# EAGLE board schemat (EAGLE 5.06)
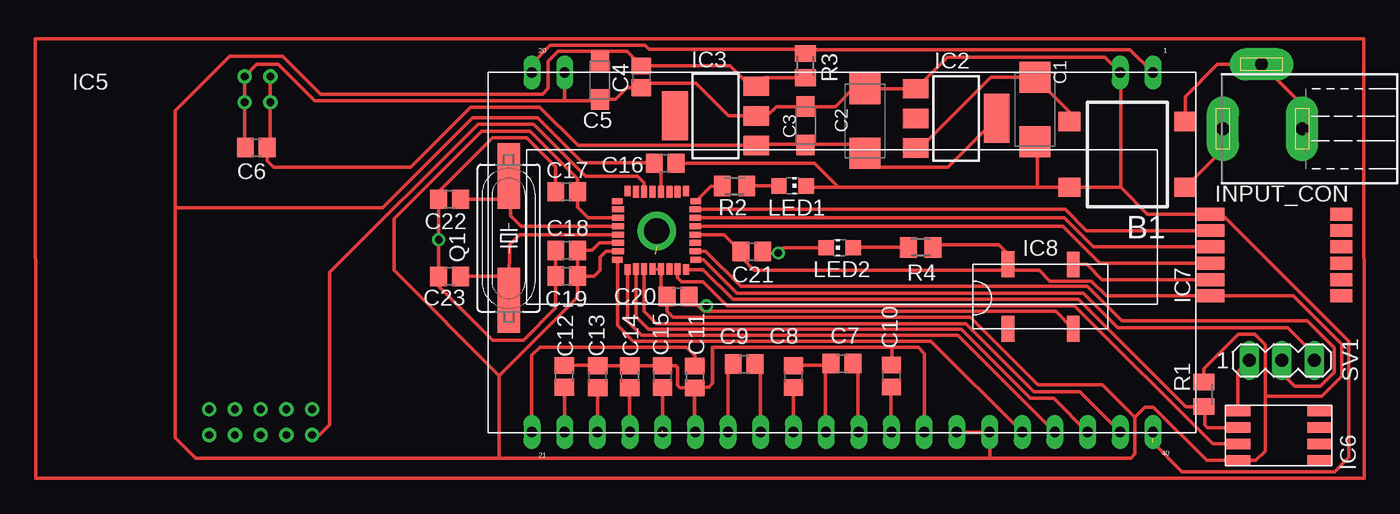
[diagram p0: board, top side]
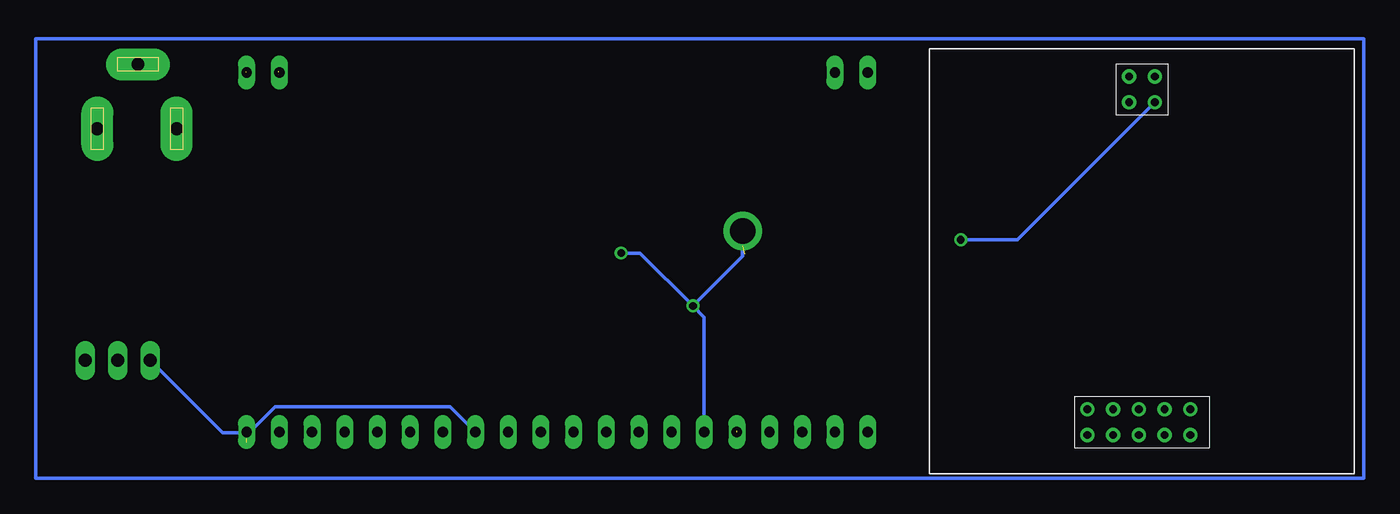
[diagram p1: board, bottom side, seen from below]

No outline drawn. Coordinates in mm, seen from the top.
Copper layers (1*16): Top 0.035mm / dielectric 1.5mm / Bottom 0.035mm
Design rules "default": minimum track width 10mil, minimum drill 24mil, track to track 8mil, track to pad 8mil, pad to pad 8mil, via to via 8mil, smd to smd 8mil, copper to edge 40mil, drill to drill 8mil, minimum pad ring 10mil, minimum via ring 8mil, stop-mask expansion 4mil, vias tented up to drill 0mil, thermal gap 10mil

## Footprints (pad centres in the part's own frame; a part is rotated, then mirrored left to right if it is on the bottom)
B40S = smd 1.5 x 1.7: + -2.55,-4.5; - 2.55,-4.5; AC1 -2.55,4.5; AC2 2.55,4.5
SMC_C = smd 2.4 x 2.4: + -2.5,0; - 2.5,0
SMC_A = smd 1.6 x 1.4: + -1.5,0; - 1.5,0
C0805 = smd 1.3 x 1.5: 1 -0.85,0; 2 0.85,0
SOT223 = smd 1.5 x 2: 1 -2.3,-3.15; 2 0,-3.15; 3 2.3,-3.15 | smd 3.8 x 2: 4 0,3.15
733980-62 = drill 1 pad 2.5 long: 1 0,8.57; 2 0,2.42; 3 5,5.57
CHIP-LED0805 = smd 1.2 x 1.2: A 0,-1.05; C 0,1.05
SM49 = smd 5.08 x 1.778: 1 -4.826,0; 2 4.826,0
M0805 = smd 1.3 x 1.6: 1 -0.95,0; 2 0.95,0
MA03-1 = drill 1.016 long: 1 -2.54,0; 2 0,0; 3 2.54,0
EFM32G210 = smd 0.82 x 0.47: 1 -0.05,0; 8 -0.05,-4.55; 17 6.05,-4.55; 24 6.05,0 | smd 0.92 x 0.47: 2 0,-0.65; 3 0,-1.3; 4 0,-1.95; 5 0,-2.6; 6 0,-3.25; 7 0,-3.9; 18 6,-3.9; 19 6,-3.25; 20 6,-2.6; 21 6,-1.95; 22 6,-1.3; 23 6,-0.65 | smd 0.47 x 0.82: 9 0.72,-5.33; 16 5.27,-5.33; 25 5.27,0.77; 32 0.72,0.77 | smd 0.47 x 0.92: 10 1.37,-5.28; 11 2.02,-5.28; 12 2.67,-5.28; 13 3.32,-5.28; 14 3.97,-5.28; 15 4.62,-5.28; 26 4.62,0.72; 27 3.97,0.72; 28 3.32,0.72; 29 2.67,0.72; 30 2.02,0.72; 31 1.37,0.72
SHT10 = smd 1.9 x 0.8: 1 -3.81,6.35; 2 -3.81,5.08; 3 -3.81,3.81; 4 -3.81,2.54; P$5 2.54,6.35; P$6 2.54,5.08; P$7 2.54,3.81; P$8 2.54,2.54
MS5534A = smd 2.2 x 1: 1 6.35,2.54; 2 6.35,3.81; 3 6.35,5.08; 4 6.35,6.35; 5 6.35,7.62; 6 6.35,8.89 | smd 1.7 x 1: P$1 -3.81,8.89; P$2 -3.81,7.62; P$3 -3.81,6.35; P$4 -3.81,5.08; P$5 -3.81,3.81; P$6 -3.81,2.54
S100 = drill 0.6 round: 1 15.3,-2.15; 2 13.3,-2.15; 3 15.3,-4.15; 4 13.3,-4.15; 5 18.55,-28; 6 18.55,-30; 7 16.55,-28; 8 16.55,-30; 9 14.55,-28; 10 14.55,-30; 11 12.55,-28; 12 12.55,-30; 13 10.55,-28; 14 10.55,-30
SG3032 = smd 1 x 2: 1 2.71,-5; 2 7.78,-5.01; 3 7.78,-0.01; 4 2.71,0
E_DOG-M_DISPLAY = drill 0.8 long: 1 3.334,0; 2 5.874,0; 19 49.054,0; 20 51.594,0; 21 51.594,27.94; 22 49.054,27.94; 23 46.514,27.94; 24 43.974,27.94; 25 41.434,27.94; 26 38.894,27.94; 27 36.354,27.94; 28 33.814,27.94; 29 31.274,27.94; 30 28.734,27.94; 31 26.194,27.94; 32 23.654,27.94; 33 21.114,27.94; 34 18.574,27.94; 35 16.034,27.94; 36 13.494,27.94; 37 10.954,27.94; 38 8.414,27.94; 39 5.874,27.94; 40 3.334,27.94

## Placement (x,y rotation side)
B1  RECTIFIER-B40S  [B40S]  122,32 270 top
C1  10 uF  [SMC_C]  114.8,35.5 270 top
C2  22 uF  [SMC_C]  101.61,34.59 90 top
C3  4.7 uF  [SMC_A]  97,34.23 90 top
C4  1uF  [C0805]  84.23,38.03 90 top
C5  10 uF  [SMC_A]  81,37.77 270 top
C6  1uF  [C0805]  54.3,32.53 0 top
C7  1uF  [C0805]  99.82,15.76 180 top
C8  1uF  [C0805]  96.05,14.74 270 top
C9  1uF  [C0805]  92.21,15.71 0 top
C10  1uF  [C0805]  103.66,14.79 90 top
C11  1uF  [C0805]  88.38,14.72 270 top
C12  1uF  [C0805]  78.24,14.76 90 top
C13  1uF  [C0805]  80.84,14.74 90 top
C14  1uF  [C0805]  83.33,14.74 90 top
C15  1uF  [C0805]  85.87,14.74 90 top
C16  100 nF  [C0805]  86.08,31.32 180 top
C17  10 nF  [C0805]  78.43,29.1 0 top
C18  100 nF  [C0805]  78.43,24.54 0 top
C19  10 nF  [C0805]  78.42,22.56 0 top
C20  1 uF  [C0805]  87.08,20.96 180 top
C21  100 nF  [C0805]  92.82,24.45 180 top
C22  12 pF  [C0805]  69.33,28.52 180 top
C23  12 pF  [C0805]  69.33,22.52 180 top
IC2  LM1117-5.0  [SOT223]  108.7,34.8 270 top
IC3  MCP1825  [SOT223]  90,35 90 top
INPUT_CON  [733980-62]  138,34 90 top
LED1  [CHIP-LED0805]  95.97,29.57 270 top
LED2  [CHIP-LED0805]  99.66,24.75 90 top
Q1  8.00 MHz  [SM49]  73.93,25.5 90 top
R1  10k  [M0805]  127.94,13.36 90 top
R2  100  [M0805]  91.47,29.54 180 top
R3  100  [M0805]  96.98,38.9 270 top
R4  100  [M0805]  105.94,24.77 0 top
SV1  [MA03-1]  134,16 0 top
U$1  EFM32G210  [EFM32G210]  87.7,29.1 270 top
U$2  SHT10  [SHT10]  134.4,5.7 0 top
U$3  MS5534A  [MS5534A]  134.8,29.9 180 top
U$4  S100  [S100]  40.1,40.2 0 top
U$5  SG3032  [SG3032]  110,23.47 0 top
U$6  EA_DOG-M_DISPLAY  [E_DOG-M_DISPLAY]  127.32,38.37 180 top

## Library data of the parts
B1 = rectifier
C1-C23 R1-R4 = rcl
IC2 IC3 = v-reg
INPUT_CON = con-conrad
LED1 LED2 = led
Q1 = crystal
SV1 = con-lstb
U$1 = EFM32G210
U$2 = SHT10
U$3 = MS5534A
U$4 = S100
U$5 = SG3032
U$6 = display_ea_dogm132

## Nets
+3V3: C4.2 C5.+ C16.2 C17.2 C18.2 C19.2 C20.2 C21.2 IC3.3 R1.2 R3.2 R4.2 U$1.4 U$1.11 U$1.14 U$1.15 U$1.20 U$1.21 U$1.28 U$2.4 U$3.6 U$5.4 U$6.34 U$6.35
GND: B1.- C1.- C2.- C3.- C4.1 C5.- C6.1 C10.2 C11.2 C12.2 C13.2 C14.2 C15.2 C16.1 C17.1 C18.1 C19.1 C20.1 C21.1 C22.2 C23.2 IC2.1 IC3.2 LED1.C LED2.C SV1.1 U$2.1 U$3.1 U$4.2 U$4.4 U$5.2 U$6.2 U$6.19 U$6.26 U$6.33 U$6.40
N$2: B1.+ C1.+ IC2.3
N$3: U$3.5 U$5.3
N$4: B1.AC1 INPUT_CON.3
N$6: B1.AC2 INPUT_CON.1
N$7: U$1.6 U$4.6
N$8: U$1.29 U$3.4
N$9: R1.1 U$1.24 U$2.2
N$10: R3.1 U$6.1 U$6.20
N$11: U$1.23 U$2.3
N$12: C7.1 U$6.31
N$13: C13.1 U$6.23
N$14: C12.1 U$6.22
N$15: C11.1 U$6.21
N$16: C14.1 U$6.24
N$17: C15.1 U$6.25
N$18: C9.1 U$6.27
N$19: C7.2 C8.1 U$6.30
N$20: C8.2 U$6.29
N$21: C9.2 U$6.28
N$22: C10.1 U$6.32
N$23: R2.2 U$1.32
N$24: U$1.19 U$6.39
N$25: U$1.18 U$6.38
N$26: U$1.17 U$6.37
N$27: U$1.16 U$6.36
N$28: U$1.30 U$3.3
N$29: U$1.31 U$3.2
N$30: C23.1 Q1.1 U$1.13
N$31: C22.1 Q1.2 U$1.12
N$32: LED1.A R2.1
N$33: LED2.A R4.1
N$36: SV1.2 U$1.26
N$37: SV1.3 U$1.25
VDD: C2.+ C3.+ C6.2 IC2.4 IC3.1 U$4.1 U$4.3

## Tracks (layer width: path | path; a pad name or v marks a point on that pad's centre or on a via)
+3V3
  Top 0.254: 111.31,10.43 U$6.35 U$6.34 | 111.31,10.43 | C17.2 79.28,29.28 | U$1.14 80.97,25.13 80.38,24.54 C18.2 C19.2 | U$1.15 81.48,24.48 81,24 81,23 80.56,22.56 C19.2 | U$1.20 U$1.21 85.75,21.43 C20.2 86.22,19.83 86.7,19.36 109.79,19.36 115.03,14.11 120.08,14.11 122.59,11.59 | 113,8.41 122.27,8.41 122.59,8.73 122.59,11.59 | 113,8.41 111.81,8.41 | 122.59,11.59 123.37,12.37 124.03,12.37 128.16,8.24 U$2.4 132,8.24 132.72,8.96 132.72,13.2 | U$1.28 90.64,25.78 C21.2 92,24.42 92,24 93,23 112,23 | 112,23 112.25,23 U$5.4 112.71,24.29 112,25 106.89,25 R4.2 | R1.2 127.94,15.34 130.63,18.02 131.89,18.02 132.72,17.2 132.72,13.2 | 112,23 115.16,23 116,22.16 119.2,22.16 120.35,21.01 U$3.6 134.89,21.01 138.66,17.24 138.66,14.76 137.1,13.2 132.72,13.2 | R3.2 93.8,37.95 IC3.3 92.7,37.3 91.12,38.88 C4.2 83.11,40 81,40 | 85.23,31.07 85.75,30.55 U$1.4 | 85.23,31.07 C16.2 | 81,40 77.76,40 76.99,39.23 76.99,37.13 76.54,36.68 59.32,36.68 56.36,39.64 52.25,39.64 48,35.39 48,28 | 48,28 48,10 49.59,8.41 73,8.41 | C19.2 79.27,20.92 73.18,14.82 | C17.2 79.28,30.11 75.56,33.82 71.82,33.82 65,27 65,23 73.18,14.82 | U$1.11 80.11,27.08 79.28,27.91 C17.2 | 85.23,31.07 84.94,31.36 79.65,31.36 76.16,34.85 71.11,34.85 64.13,27.86 48.14,27.86 48,28 | 73,8.41 111,8.41 | 111,8.41 113,8.41 | 111.31,10.43 111.31,8.41 111,8.41 | 73.18,14.82 73.18,8.41 73,8.41 | 81,40 C5.+
GND  (via drill 0.6)  (2 unrouted)
  Top 0.254: C11.2 88.38,13.79 88.38,10.94 | 88.38,10.94 88.38,10.52 | C12.2 | C12.2 80.83,15.61 C13.2 83.27,15.59 83.27,15.58 83.27,15.59 C14.2 85.76,15.59 85.76,15.58 85.76,15.59 C15.2 86.93,15.59 87.06,15.46 87.06,14.06 87.23,13.88 88.35,13.88 C11.2 | 88,13.86 88.01,13.87 C11.2 | 103.64,15.66 103.62,15.66 | 103.64,15.66 C10.2 | C11.2 88.38,13.91 88.48,13.91 89.47,13.91 89.78,14.21 89.78,17.01 103.69,17.01 | 88.38,10.94 88.45,10.94 88.45,10.43 U$6.26 | 103.64,15.66 103.69,15.72 103.69,17.01 | 103.69,17.01 105.75,17.01 106.23,16.52 106.23,10.46 U$6.33 106.23,10.4 | 123.98,9.92 124.01,9.95 | 121.47,38.4 U$6.2 120.24,39.57 108.02,39.57 IC2.1 102,37.1 | 68.48,25 C23.2 | 68.48,25 C22.2 68.48,29.1 72.67,33.3 75.31,33.3 77.58,31.03 C17.1 | C18.1 C19.1 77.57,20.08 75.08,17.59 72.65,17.59 68.48,21.76 C23.2 | C23.2 68.15,22.85 | U$6.40 v124.02,10.39 | 87.92,20.45 C20.1 88.94,19.94 | 102,37.1 101.75,37.1 | SV1.1 130.59,15.13 U$2.1 | 88.94,19.94 89.08,19.8 | 89.08,19.8 116.44,19.8 | 116.44,19.8 U$5.2 | 116.44,19.8 116.44,19.79 | 121.47,29.45 B1.- 115,29.45 | 121.47,29.45 121.47,38.47 | 121.47,29.45 123.56,27.36 U$3.1 129.33,27.36 139.21,17.48 139.21,8.47 138.1,7.37 126.25,7.37 123.98,9.63 123.98,10.35 v124.02,10.39 | 77,36.18 77.33,36.18 | C1.- 115,32.8 115,29.45 | v124.02,10.39 124,10.37 | v68.48,25.37 68.48,25 | 89.08,19.8 89.18,19.8 | C21.1 93.67,24.34 v94.88,24.34 95.28,24.75 LED2.C | v89.3,20.23 89.01,19.94 88.94,19.94 | C16.1 97.68,31.32 99.55,29.45 100,29.45 | 115,29.45 100,29.45 | LED1.C 97.14,29.45 100,29.45 | 102,37.1 101.99,37.09 C2.- 100.93,37.09 100.8,37.22 99.3,35.73 C3.- 94.72,35.73 94,35 IC3.2 91,35 88.46,37.54 84.72,37.54 84.36,37.18 C4.1 83.13,37.18 82.23,36.27 C5.- 80.68,36.18 78,36.18
  Top 0.254: 77,36.18 78,36.18 | U$6.19 78.26,36.18 78,36.18 | C6.1 arc-90 53.4,32.58 U$4.4 U$4.2 54.35,39 56,39 58.82,36.18 77,36.18
  Bottom 0.254: SV1.1 125.85,10.39 v124.02,10.39 | v94.88,24.34 93.41,24.34 v89.3,20.23 88.42,19.36 U$6.26 | U$6.40 123.75,10.43 121.76,12.41 108.19,12.41 U$6.33 | v68.48,25.37 64.08,25.37 U$4.4
N$1
  Top 0.254: 37.17,6.85 37.14,40.99 140.36,40.99 140.39,6.85 37.17,6.85
N$2
  Top 0.254: B1.+ 117.5,35.3 C1.+ 111.4,38 105.9,32.5 IC2.3
N$3
  Top 0.254: U$3.5 120.02,22.28 118.84,23.46 U$5.3
N$4
  Top 0.254: INPUT_CON.3 129,39 126.5,36.5 B1.AC1
N$5
  Bottom 0.254: 37.15,40.99 37.16,6.85 140.39,6.85 140.36,41.01
N$6
  Top 0.254: INPUT_CON.1 129.43,32.38 B1.AC2
N$7
  Top 0.254: U$1.6 84.45,29.79 83.94,30.3 79.89,30.3 75.83,34.36 71.53,34.36 60,22.83 60,11 59.2,10.2 U$4.6
N$8
  Top 0.254: U$3.4 119.87,23.55 116.99,26.43 U$1.29
N$9
  Top 0.254: U$1.24 89.03,23.05 91.35,20.73 118.2,20.73 126.53,12.41 R1.1 128,12.36 128,11 128.22,10.78 U$2.2
N$10  (1 unrouted)
  Top 0.254: 124.01,38.37 U$6.1 122.2,40.15 96.98,40.15 R3.1 | 123.96,38.44 124.01,38.44 | R3.1 96.98,40.15 | U$6.20 75.72,39.06 77.14,40.48 84.52,40.48 84.84,40.16 96.98,40.16 R3.1
N$11
  Top 0.254: U$1.23 87.05,22.4 87.33,22.12 89.02,22.12 90.88,20.27 117.87,20.27 128.62,9.51 U$2.3
N$12
  Top 0.254: C7.1 101.08,15.35 101.08,10.56 101.15,10.56 101.15,10.43 U$6.31
N$13
  Top 0.254: C13.1 80.81,13.86 80.81,10.68 | 80.81,10.68 80.81,10.35 | 80.81,10.68 80.83,10.68 80.83,10.43 U$6.23
N$14
  Top 0.254: C12.1 78.24,10.94 | 78.24,10.94 78.24,10.5 | 78.24,10.94 78.29,10.94 78.29,10.43 U$6.22
N$15
  Top 0.254: 88.38,16.14 C11.1 88.4,15.59 88.4,16.37 87.74,17.03 77.28,17.03 | 77.28,17.03 76.77,17.03 | 75.7,10.94 75.7,10.53 | 75.7,10.94 75.7,16.4 76.34,17.03 77.28,17.03 | 75.7,10.94 75.75,10.94 75.75,10.43 U$6.21
N$16
  Top 0.254: C14.1 83.32,13.86 83.32,10.22 83.37,10.22 83.37,10.43 | 83.37,10.43 | U$6.24 83.37,10.43 | 83.37,10.43 83.37,10.94
N$17  (1 unrouted)
  Top 0.254: C15.1 85.86,10.52
N$18
  Top 0.254: C9.1 90.94,15.71 90.94,10.68 | 90.94,10.68 90.94,10.52 | 90.94,10.68 90.74,10.68 90.74,10.43 U$6.27
N$19
  Top 0.254: 98.54,15.33 C7.2 | 98.54,15.33 98.54,10.3 98.61,10.3 | C8.1 96.05,15.61 98.54,15.61 98.54,15.33 | 98.61,10.3 98.61,10.17 | U$6.30 98.61,10.43 98.61,10.3
N$20
  Top 0.254: C8.2 U$6.29 96.07,10.43 | 96.07,10.43 96.07,10.17 | U$6.29 96.07,10.43 | 96.07,10.43
N$21
  Top 0.254: C9.2 93.48,15.71 93.48,10.68 | 93.48,10.68 93.48,10.52 | 93.48,10.68 93.53,10.68 93.53,10.43 U$6.28
N$22
  Top 0.254: C10.1 103.64,13.92 103.64,10.68 | 103.64,10.68 103.64,10.53 | 103.64,10.68 103.69,10.68 103.69,10.43 U$6.32
N$23
  Top 0.254: U$1.32 89.63,29.54 R2.2
N$24
  Top 0.254: U$1.19 84.45,19.83 85.42,18.86 109.46,18.86 114.75,13.57 118.3,13.57 U$6.39
N$25
  Top 0.254: U$1.18 83.8,19.39 84.79,18.4 109.09,18.4 114.45,13.04 116.28,13.04 U$6.38
N$26
  Top 0.254: U$1.17 83.15,19.03 84.23,17.95 108.84,17.95 U$6.37
N$27
  Top 0.254: U$1.16 82.37,18.72 83.58,17.5 106.75,17.5 U$6.36
N$28
  Top 0.254: U$3.3 119.35,24.82 117.09,27.08 U$1.30
N$29
  Top 0.254: U$3.2 118.83,26.09 117.19,27.73 U$1.31
N$30
  Top 0.254: 73.95,21.98 Q1.1 73.18,20.67 | 73.95,21.98 74,25 74.78,25.78 U$1.13 | C23.1 73.42,22.52 73.95,21.98
N$31
  Top 0.254: Q1.2 74.24,30.32 | Q1.2 73.61,30 | U$1.12 74.87,26.43 74.08,27.22 74.08,28 | 74.08,28 74.08,30.17 Q1.2 | C22.1 73.56,28.52 74.08,28
N$32
  Top 0.254: R2.1 92.44,29.57 LED1.A
N$33
  Top 0.254: LED2.A 100.7,24.77 R4.1
N$34
  Bottom 0.254: 37.15,41 140.36,41 140.36,24.78 140.37,24.78 140.39,6.85
N$35  (1 unrouted)
  Bottom 0.254: 89.31,20.25 85.45,24.11 85.45,24.92
N$36
  Top 0.254: U$1.26 89.23,24.48 91.97,21.74 118.88,21.74 121.56,19.06 135.99,19.06 138.07,16.99 138.07,15.07 137,14 135,14 134,15 SV1.2
N$37
  Top 0.254: U$1.25 89.08,23.83 91.67,21.24 118.59,21.24 121.28,18.55 134.45,18.55 136.54,16.46 SV1.3
N$39  (via drill 2)
  other vias: 85.43,26.05
N$40
  Top 0.254: 135.58,33.98 135.58,35.88 132.44,39.01
VDD
  Top 0.254: U$4.1 U$4.3 55.4,32.78 arc-90 C6.2 55.15,31.51 55.66,31 56,31 66.3,31 70.98,35.68 76.32,35.68 79.3,32.7 IC3.1 arc-90 93.25,32.8 97,32.8 C3.+ 97,32.81 100.94,32.81 | IC2.4 108.05,31 101,31 100.8,31.2 101.61,32.01 C2.+ 100.94,32.76 100.94,32.81 | 100.94,32.81 100.8,32.66

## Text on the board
tPlace: IC5 | C5 | IC8 | IC7 | IC6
